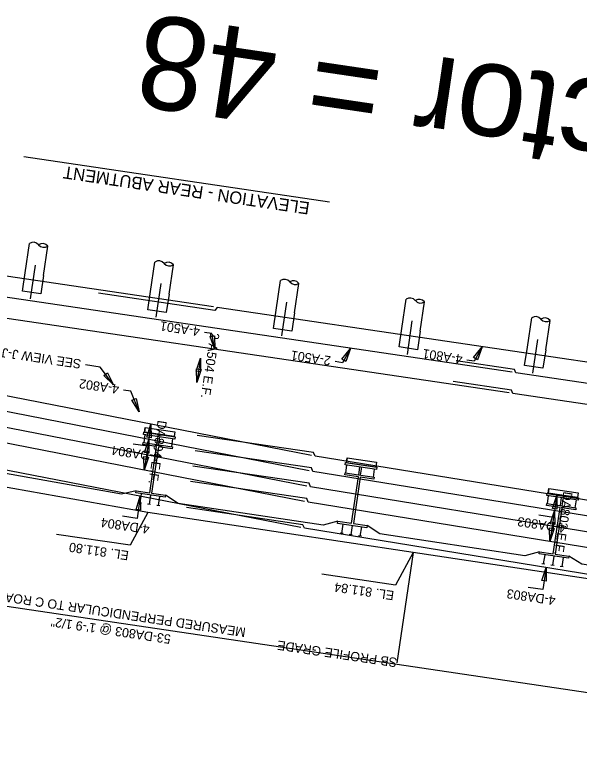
# Model space of a CAD drawing. Extents: x 1468952 to 1469933, y 573916 to 574220.
# Drawn here: x 1469019.53 to 1469049.93, y 574056.5 to 574095.95 of the extents above; entities that cross this region are included whole.
import ezdxf

# ---------------------------------------------------------------- set-up
doc = ezdxf.new("R2010")
doc.units = 0
for name, color, linetype in [('BR_P_Beam_Stl_Det', 7, 'Continuous'), ('BR_P_Gen_Phase_Construction', 7, 'Continuous'), ('BR_P_Sub_Centerline', 7, 'Continuous'), ('BR_P_Sub_Foot_Centerline', 7, 'Continuous'), ('BR_P_Sub_Text', 7, 'Continuous'), ('BR_X_SV_Beam_Seat', 7, 'Continuous'), ('Default', 7, 'Continuous'), ('GE_P_CL_50', 7, 'Continuous'), ('GK_Cells', 7, 'Continuous'), ('PF_X_Ground_Line', 7, 'Continuous'), ('SV_X_Text_Elevation', 7, 'Continuous'), ('UT_X_Water', 7, 'Continuous')]:
    doc.layers.add(name, color=color, linetype=linetype)

# ---------------------------------------------------------------- blocks, each defined once
blk = doc.blocks.new('arrowOhio')
at = {"layer": 'Default'}
blk.add_lwpolyline([(0.00381, 0.000635), (0.00381, -0.000635), (0, 0)], close=True, dxfattribs=at)

msp = doc.modelspace()

# ---------------------------------------------------------------- linework, layer by layer
at = {"layer": 'BR_P_Beam_Stl_Det'}
for points in [[(1469030.229, 574080.212), (1469004.495, 574084.021), (1469004.371, 574083.865), (1468998.106, 574084.792)], [(1469046.308, 574076.694), (1469010.886, 574081.938), (1469010.812, 574082.124), (1469007.68, 574082.588)], [(1469046.144, 574075.581), (1469010.721, 574080.825), (1469010.648, 574081.011), (1469007.515, 574081.475)], [(1469056.161, 574076.372), (1469030.427, 574080.182), (1469030.303, 574080.026), (1469024.038, 574080.953)], [(1469082.126, 574071.391), (1469046.506, 574076.665), (1469046.433, 574076.85), (1469043.3, 574077.314)], [(1469081.962, 574070.278), (1469046.341, 574075.552), (1469046.268, 574075.738), (1469043.135, 574076.201)]]:
    msp.add_lwpolyline(points, dxfattribs=at)
at = {"layer": 'BR_P_Gen_Phase_Construction'}
for p, q in [((1469020.089, 574082.05), (1469020.323, 574083.632)), ((1469021.078, 574081.903), (1469021.313, 574083.486)), ((1469026.849, 574081.049), (1469027.083, 574082.632)), ((1469027.838, 574080.902), (1469028.072, 574082.485)), ((1469033.608, 574080.048), (1469033.843, 574081.631)), ((1469034.598, 574079.902), (1469034.832, 574081.484)), ((1469040.368, 574079.047), (1469040.602, 574080.63)), ((1469041.357, 574078.901), (1469041.592, 574080.484)), ((1469047.128, 574078.047), (1469047.362, 574079.629)), ((1469048.117, 574077.9), (1469048.351, 574079.483))]:
    msp.add_line(p, q, dxfattribs=at)
for centre, start, end in [((1469020.532, 574083.336), 37.976, 125.1816), ((1469021.027, 574083.263), 37.976, 125.1816), ((1469021.104, 574083.782), 217.976, 305.1816), ((1469027.292, 574082.335), 37.976, 125.1816), ((1469027.787, 574082.262), 37.976, 125.1816), ((1469027.863, 574082.782), 217.976, 305.1816), ((1469034.052, 574081.335), 37.976, 125.1816), ((1469034.546, 574081.261), 37.976, 125.1816), ((1469034.623, 574081.781), 217.976, 305.1816), ((1469040.811, 574080.334), 37.976, 125.1816), ((1469041.306, 574080.261), 37.976, 125.1816), ((1469041.383, 574080.78), 217.976, 305.1816), ((1469047.571, 574079.333), 37.976, 125.1816), ((1469048.065, 574079.26), 37.976, 125.1816), ((1469048.142, 574079.779), 217.976, 305.1816)]:
    msp.add_arc(centre, 0.362, start, end, dxfattribs=at)
at = {"layer": 'BR_P_Sub_Centerline'}
for p, q in [((1469019.943, 574081.06), (1469020.089, 574082.05)), ((1469021.078, 574081.903), (1469020.932, 574080.914)), ((1469020.932, 574080.914), (1469019.943, 574081.06)), ((1469026.702, 574080.06), (1469026.849, 574081.049)), ((1469027.838, 574080.902), (1469027.692, 574079.913)), ((1469027.692, 574079.913), (1469026.702, 574080.06)), ((1469033.462, 574079.059), (1469033.608, 574080.048)), ((1469034.598, 574079.902), (1469034.451, 574078.913)), ((1469034.451, 574078.913), (1469033.462, 574079.059)), ((1469040.222, 574078.058), (1469040.368, 574079.047)), ((1469041.357, 574078.901), (1469041.211, 574077.912)), ((1469041.211, 574077.912), (1469040.222, 574078.058)), ((1469046.981, 574077.058), (1469047.128, 574078.047)), ((1469048.117, 574077.9), (1469047.97, 574076.911)), ((1469047.97, 574076.911), (1469046.981, 574077.058))]:
    msp.add_line(p, q, dxfattribs=at)
at = {"layer": 'BR_P_Sub_Foot_Centerline'}
for p, q in [((1469026.492, 574072.911), (1469026.554, 574073.333)), ((1469027.189, 574072.808), (1469027.251, 574073.23)), ((1469027.288, 574072.793), (1469027.35, 574073.216)), ((1469027.985, 574072.69), (1469028.047, 574073.112)), ((1469037.353, 574071.273), (1469037.415, 574071.695)), ((1469038.05, 574071.17), (1469038.112, 574071.592)), ((1469038.149, 574071.155), (1469038.211, 574071.577)), ((1469038.846, 574071.052), (1469038.908, 574071.474)), ((1469048.212, 574069.625), (1469048.275, 574070.047)), ((1469048.909, 574069.521), (1469048.972, 574069.944)), ((1469049.008, 574069.507), (1469049.071, 574069.929)), ((1469049.705, 574069.404), (1469049.768, 574069.826))]:
    msp.add_line(p, q, dxfattribs=at)
at = {"layer": 'BR_P_Sub_Text'}
for p, q in [((1469035.5, 574072.215), (1469013.917, 574076.431)), ((1469035.378, 574071.387), (1469013.795, 574075.603)), ((1469035.255, 574070.56), (1469013.672, 574074.776)), ((1469035.133, 574069.732), (1469013.55, 574073.948)), ((1469035.624, 574072.371), (1469029.359, 574073.299)), ((1469034.925, 574068.328), (1469013.342, 574072.545)), ((1469035.502, 574071.544), (1469029.237, 574072.471)), ((1469035.698, 574072.185), (1469035.624, 574072.371)), ((1469057.382, 574068.654), (1469035.698, 574072.185)), ((1469035.379, 574070.716), (1469029.114, 574071.644)), ((1469035.575, 574071.358), (1469035.502, 574071.544)), ((1469057.26, 574067.826), (1469035.575, 574071.358)), ((1469035.257, 574069.889), (1469028.992, 574070.816)), ((1469035.453, 574070.53), (1469035.379, 574070.716)), ((1469057.137, 574066.999), (1469035.453, 574070.53)), ((1469035.33, 574069.703), (1469035.257, 574069.889)), ((1469057.015, 574066.171), (1469035.33, 574069.703)), ((1469035.049, 574068.485), (1469028.784, 574069.413)), ((1469035.123, 574068.299), (1469035.049, 574068.485)), ((1469056.807, 574064.767), (1469035.123, 574068.299))]:
    msp.add_line(p, q, dxfattribs=at)
at = {"layer": 'BR_X_SV_Beam_Seat'}
msp.add_line((1469040.98, 574066.988), (1469040.101, 574061.053), dxfattribs=at)
at = {"layer": 'GE_P_CL_50'}
for p, q in [((1469026.563, 574073.722), (1469026.525, 574073.464)), ((1469026.457, 574073.348), (1469026.476, 574073.471)), ((1469028.144, 574073.098), (1469026.457, 574073.348)), ((1469026.476, 574073.471), (1469028.163, 574073.222)), ((1469028.151, 574073.487), (1469028.113, 574073.229)), ((1469028.163, 574073.222), (1469028.144, 574073.098)), ((1469037.424, 574072.083), (1469037.386, 574071.826)), ((1469037.318, 574071.71), (1469037.337, 574071.833)), ((1469039.005, 574071.46), (1469037.318, 574071.71)), ((1469037.337, 574071.833), (1469039.024, 574071.583)), ((1469039.012, 574071.848), (1469038.974, 574071.591)), ((1469039.024, 574071.583), (1469039.005, 574071.46)), ((1469048.284, 574070.435), (1469048.246, 574070.178)), ((1469048.178, 574070.061), (1469048.196, 574070.185)), ((1469049.865, 574069.812), (1469048.178, 574070.061)), ((1469048.196, 574070.185), (1469049.883, 574069.935)), ((1469049.872, 574070.2), (1469049.833, 574069.943)), ((1469049.883, 574069.935), (1469049.865, 574069.812))]:
    msp.add_line(p, q, dxfattribs=at)
for points in [[(1469028.151, 574073.487), (1469028.113, 574073.229), (1469026.525, 574073.464), (1469026.563, 574073.722)], [(1469039.012, 574071.848), (1469038.974, 574071.591), (1469037.386, 574071.826), (1469037.424, 574072.083)], [(1469049.872, 574070.2), (1469049.833, 574069.943), (1469048.246, 574070.178), (1469048.284, 574070.435)]]:
    msp.add_lwpolyline(points, close=True, dxfattribs=at)
at = {"layer": 'GK_Cells'}
for p, q in [((1469026.434, 574072.804), (1469026.451, 574072.917)), ((1469027.172, 574072.694), (1469026.434, 574072.804)), ((1469026.451, 574072.917), (1469028.026, 574072.684)), ((1469026.803, 574070.201), (1469027.172, 574072.694)), ((1469027.271, 574072.68), (1469026.902, 574070.186)), ((1469028.009, 574072.571), (1469027.271, 574072.68)), ((1469028.026, 574072.684), (1469028.009, 574072.571)), ((1469037.295, 574071.165), (1469037.312, 574071.279)), ((1469037.312, 574071.279), (1469038.887, 574071.046)), ((1469038.033, 574071.056), (1469037.295, 574071.165)), ((1469037.664, 574068.563), (1469038.033, 574071.056)), ((1469038.132, 574071.042), (1469037.763, 574068.548)), ((1469038.87, 574070.932), (1469038.132, 574071.042)), ((1469038.887, 574071.046), (1469038.87, 574070.932)), ((1469026.048, 574070.197), (1469026.065, 574070.31)), ((1469027.623, 574069.964), (1469026.048, 574070.197)), ((1469026.065, 574070.31), (1469026.803, 574070.201)), ((1469026.341, 574070.153), (1469026.268, 574069.659)), ((1469026.836, 574070.08), (1469026.762, 574069.586)), ((1469026.902, 574070.186), (1469027.64, 574070.077)), ((1469027.64, 574070.077), (1469027.623, 574069.964)), ((1469026.35, 574069.647), (1469026.185, 574069.671)), ((1469027.33, 574070.007), (1469027.257, 574069.512)), ((1469048.154, 574069.517), (1469048.171, 574069.631)), ((1469048.171, 574069.631), (1469049.746, 574069.397)), ((1469026.845, 574069.573), (1469026.68, 574069.598)), ((1469027.339, 574069.5), (1469027.175, 574069.524)), ((1469048.892, 574069.408), (1469048.154, 574069.517)), ((1469048.523, 574066.914), (1469048.892, 574069.408)), ((1469048.992, 574069.393), (1469048.622, 574066.9)), ((1469049.73, 574069.284), (1469048.992, 574069.393)), ((1469049.746, 574069.397), (1469049.73, 574069.284)), ((1469036.909, 574068.558), (1469036.926, 574068.672)), ((1469038.484, 574068.325), (1469036.909, 574068.558)), ((1469036.926, 574068.672), (1469037.664, 574068.563)), ((1469037.202, 574068.515), (1469037.129, 574068.02)), ((1469037.697, 574068.442), (1469037.623, 574067.947)), ((1469037.763, 574068.548), (1469038.501, 574068.439)), ((1469038.501, 574068.439), (1469038.484, 574068.325)), ((1469038.191, 574068.369), (1469038.118, 574067.874)), ((1469037.211, 574068.008), (1469037.046, 574068.033)), ((1469037.706, 574067.935), (1469037.541, 574067.959)), ((1469038.2, 574067.862), (1469038.035, 574067.886)), ((1469047.768, 574066.91), (1469047.785, 574067.024)), ((1469049.344, 574066.677), (1469047.768, 574066.91)), ((1469047.785, 574067.024), (1469048.523, 574066.914)), ((1469048.061, 574066.867), (1469047.988, 574066.372)), ((1469048.622, 574066.9), (1469049.36, 574066.79)), ((1469048.556, 574066.794), (1469048.483, 574066.299)), ((1469049.051, 574066.721), (1469048.977, 574066.226)), ((1469049.36, 574066.79), (1469049.344, 574066.677)), ((1469048.071, 574066.36), (1469047.906, 574066.385)), ((1469048.565, 574066.287), (1469048.4, 574066.311)), ((1469049.06, 574066.214), (1469048.895, 574066.238))]:
    msp.add_line(p, q, dxfattribs=at)
at = {"layer": 'PF_X_Ground_Line'}
for p, q in [((1469026.696, 574069.14), (1468981.648, 574077.187)), ((1469040.98, 574066.988), (1469026.696, 574069.14)), ((1469071.925, 574062.316), (1469040.98, 574066.988))]:
    msp.add_line(p, q, dxfattribs=at)
for points in [[(1469026.065, 574070.31), (1469025.28, 574070.134), (1469017.509, 574071.522), (1469016.821, 574072.002)], [(1469036.926, 574068.672), (1469036.135, 574068.455), (1469028.332, 574069.631), (1469027.64, 574070.077)], [(1469047.785, 574067.024), (1469046.996, 574066.817), (1469039.193, 574067.994), (1469038.501, 574068.439)], [(1469058.646, 574065.385), (1469057.857, 574065.177), (1469050.054, 574066.355), (1469049.36, 574066.79)]]:
    msp.add_lwpolyline(points, dxfattribs=at)
at = {"layer": 'SV_X_Text_Elevation'}
for p, q in [((1469036.469, 574085.858), (1469020.024, 574088.293)), ((1469030.136, 574078.787), (1469029.74, 574078.845)), ((1469030.312, 574077.925), (1469030.136, 574078.787)), ((1469037.601, 574077.983), (1469037.182, 574077.209)), ((1469044.69, 574078.071), (1469044.271, 574077.297)), ((1469029.527, 574077.451), (1469029.334, 574076.142)), ((1469037.182, 574077.209), (1469036.787, 574077.268)), ((1469044.271, 574077.297), (1469043.875, 574077.355)), ((1469024.139, 574076.976), (1469023.348, 574077.093)), ((1469024.855, 574076.013), (1469024.139, 574076.976)), ((1469025.783, 574075.677), (1469025.388, 574075.736)), ((1469026.225, 574074.562), (1469025.783, 574075.677)), ((1469026.867, 574073.901), (1469026.691, 574072.714)), ((1469026.691, 574072.714), (1469025.9, 574072.831)), ((1469026.745, 574073.074), (1469026.499, 574071.419)), ((1469070.259, 574056.497), (1468978.025, 574070.152)), ((1469026.292, 574070.015), (1469026.116, 574068.828)), ((1469048.708, 574070.066), (1469048.533, 574068.879)), ((1469048.586, 574069.239), (1469048.341, 574067.584)), ((1469026.116, 574068.828), (1469025.325, 574068.945)), ((1469026.696, 574069.14), (1469025.745, 574067.382)), ((1469048.533, 574068.879), (1469047.741, 574068.996)), ((1469025.745, 574067.382), (1469021.788, 574067.967)), ((1469040.98, 574066.988), (1469040.028, 574065.229)), ((1469048.133, 574066.18), (1469047.957, 574064.993)), ((1469040.028, 574065.229), (1469036.071, 574065.815)), ((1469047.957, 574064.993), (1469047.166, 574065.11))]:
    msp.add_line(p, q, dxfattribs=at)
at = {"layer": 'UT_X_Water'}
for p, q in [((1469020.388, 574080.657), (1469020.657, 574082.471)), ((1469027.148, 574079.657), (1469027.417, 574081.47)), ((1469033.908, 574078.656), (1469034.176, 574080.47)), ((1469040.667, 574077.655), (1469040.936, 574079.469)), ((1469047.427, 574076.655), (1469047.696, 574078.468))]:
    msp.add_line(p, q, dxfattribs=at)

# ---------------------------------------------------------------- block references
at = {"layer": 'SV_X_Text_Elevation'}
for p, xscale, yscale, rotation in [((1469030.312, 574077.925), 191.49567999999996, 191.49568, 101.57876932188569), ((1469037.601, 574077.983), 191.49568000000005, 191.49568000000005, -118.42123067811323), ((1469044.69, 574078.071), 191.49568000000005, 191.49568000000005, -118.42123067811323), ((1469029.527, 574077.451), 191.49568000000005, 191.49568, -98.42123067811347), ((1469029.334, 574076.142), 191.49568000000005, 191.49568, 81.57876932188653), ((1469024.855, 574076.013), 191.49568000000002, 191.49568000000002, 126.57876932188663), ((1469026.225, 574074.562), 191.49568000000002, 191.49568000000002, 111.57876932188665), ((1469026.867, 574073.901), 191.49568000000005, 191.49568, -98.42123067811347), ((1469026.745, 574073.074), 191.49568000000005, 191.49568, -98.42123067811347), ((1469026.499, 574071.419), 191.49568000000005, 191.49568, 81.57876932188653), ((1469026.292, 574070.015), 191.49568000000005, 191.49568, -98.42123067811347), ((1469048.708, 574070.066), 191.49568000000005, 191.49568, -98.42123067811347), ((1469048.586, 574069.239), 191.49568000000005, 191.49568, -98.42123067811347), ((1469048.341, 574067.584), 191.49568000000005, 191.49568, 81.57876932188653), ((1469048.133, 574066.18), 191.49568000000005, 191.49568, -98.42123067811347)]:
    msp.add_blockref('arrowOhio', p, dxfattribs=dict(at, xscale=xscale, yscale=yscale, rotation=rotation))

# ---------------------------------------------------------------- texts
for s, height, rotation, p in [('Scale Factor = 48', 4.99999, 171.5788, (1469078.57, 574088.343)), ('ELEVATION - REAR ABUTMENT', 0.665, 171.5788, (1469035.442, 574085.842)), ('4-A501', 0.5, 171.5788, (1469029.529, 574079.129)), ('2-A504 E.F.', 0.5, 261.5788, (1469030.066, 574078.861)), ('SEE VIEW J-J', 0.5, 171.5788, (1469023.137, 574077.377)), ('4-A801', 0.5, 171.5788, (1469043.664, 574077.639)), ('2-A501', 0.5, 171.5788, (1469036.576, 574077.551)), ('4-A802', 0.5, 171.5788, (1469025.177, 574076.02)), ('DA804 E.F.', 0.5, 261.5788, (1469027.231, 574074.132)), ('4-DA804', 0.5, 171.5788, (1469027.396, 574072.361)), ('DA803 E.F.', 0.5, 261.5788, (1469049.072, 574070.297)), ('4-DA804', 0.5, 171.5788, (1469026.821, 574068.475)), ('4-DA803', 0.5, 171.5788, (1469049.246, 574068.525)), ('EL. 811.80', 0.5, 171.5788, (1469025.697, 574067.059)), ('EL. 811.84', 0.5, 171.5788, (1469039.98, 574064.907)), ('MEASURED PERPENDICULAR TO C ROADWAY', 0.5, 171.5788, (1469031.992, 574062.924)), ('4-DA803', 0.5, 171.5788, (1469048.671, 574064.639)), ('53-DA803 @ 1\'-9 1/2"', 0.5, 171.5788, (1469027.959, 574062.557)), ('SB PROFILE GRADE ', 0.5, 171.5788, (1469040.138, 574061.3))]:
    msp.add_text(s, height=height, rotation=rotation, dxfattribs=at).set_placement(p)

doc.saveas('drawing.dxf')
